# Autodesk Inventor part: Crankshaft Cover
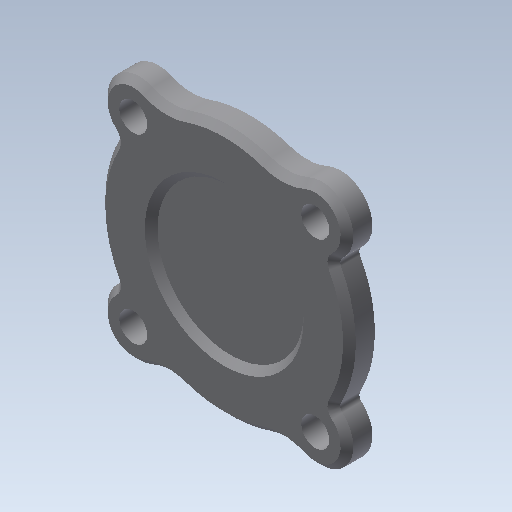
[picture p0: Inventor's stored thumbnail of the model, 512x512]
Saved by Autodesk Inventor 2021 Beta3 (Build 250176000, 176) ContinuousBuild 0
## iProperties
Created: 2013-05
Part Number: Crankshaft Cover
Material: Generic
Document SubType Name: Modeling
Designer: John
Density: 1 g/cm^3
Appearance: Default
Author: John
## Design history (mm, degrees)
sketch "Sketch1"
  geometry: C1 r 10.477 at (0, 0) reference; C2 r 0.965 at (9.093, -9.093) reference; C3 r 0.965 at (-9.093, 9.093) reference; C4 r 0.965 at (9.093, 9.093) reference; C5 r 0.965 at (-9.093, -9.093) reference; A1 r 3.175 centre (9.093, 9.093) between (11.169, 6.691) and (7.799, 11.992) reference; A2 r 5.08 centre (5.727, 16.631) between (4.073, 11.828) and (7.799, 11.992) reference; A3 r 12.509 centre (0, 0) between (4.073, 11.828) and (-4.073, 11.828) reference; A4 r 5.08 centre (-5.727, 16.631) between (-7.799, 11.992) and (-4.073, 11.828) reference; A5 r 3.175 centre (-9.093, 9.093) between (-7.799, 11.992) and (-11.169, 6.691) reference; A6 r 0.635 centre (-11.585, 6.211) between (-11.025, 5.911) and (-11.169, 6.691) reference; A7 r 12.509 centre (0, 0) between (-11.025, 5.911) and (-11.025, -5.911) reference; A8 r 0.635 centre (-11.585, -6.211) between (-11.169, -6.691) and (-11.025, -5.911) reference; A9 r 3.175 centre (-9.093, -9.093) between (-11.169, -6.691) and (-7.799, -11.992) reference; A10 r 5.08 centre (-5.727, -16.631) between (-4.073, -11.828) and (-7.799, -11.992) reference; A11 r 12.509 centre (0, 0) between (-4.073, -11.828) and (4.073, -11.828) reference; A12 r 5.08 centre (5.727, -16.631) between (7.799, -11.992) and (4.073, -11.828) reference; A13 r 3.175 centre (9.093, -9.093) between (7.799, -11.992) and (11.169, -6.691) reference; A14 r 0.635 centre (11.585, -6.211) between (11.025, -5.911) and (11.169, -6.691) reference; A15 r 12.509 centre (0, 0) between (11.025, -5.911) and (11.025, 5.911) reference; A16 r 0.635 centre (11.585, 6.211) between (11.169, 6.691) and (11.025, 5.911) reference; 1 further point
extrude "Extrusion1" new body sketch "Sketch1" distance "d0" = 2.54; taper "d1" = 0 deg
sketch "Sketch2"
  geometry: C1 r 10.477 at (0, 0) reference; C2 r 10.351 at (0, 0)
  constraints: 1 centre point, 1 coincident
  dimensions: "d2" = 0.127 radial gap between concentric circles of C1 C2
extrude "Extrusion2" join sketch "Sketch2" distance "d3" = 0.635; taper "d4" = 0 deg
sketch "Sketch3"
  geometry: C1 r 4 at (0, 0) reference; C2 r 4.026 at (0, 0); C3 r 6.566 at (0, 0)
  constraints: 2 centre point, 2 coincident
  dimensions: "d5" = 0.0254 radial gap between concentric circles of C1 C2; "d6" = 2.54 radial gap between concentric circles of C3 C2
extrude "Extrusion3" join sketch "Sketch3" distance "d7" = 3.175; taper "d8" = 0 deg
chamfer "Chamfer1" distance "d9" = 0.635; stored, may be unused: second distance "d10" = 3.175, angle "d11" = 45 deg
chamfer "Chamfer4" distance "d28" = 0.254; stored, may be unused: second distance "d29" = 3.175, angle "d30" = 45 deg
sketch "Sketch4"
  geometry: A1 r 3.175 centre (9.093, 9.093) between (11.169, 6.691) and (7.799, 11.992) reference; A2 r 3.175 centre (-9.093, 9.093) between (-7.799, 11.992) and (-11.169, 6.691) reference; A3 r 3.175 centre (-9.093, -9.093) between (-11.169, -6.691) and (-7.799, -11.992) reference; A4 r 3.175 centre (9.093, -9.093) between (7.799, -11.992) and (11.169, -6.691) reference
hole "Hole1" sketch "Sketch4" at (9.093, 9.093), (-9.093, 9.093), (-9.093, -9.093), (9.093, -9.093) diameter "d12" = 2.794; stored, may be unused: countersink angle "d16" = 82 deg, drill point angle "d18" = 118 deg; dims "d13" = 19.05, "d14" = 5.0546, "d15" = 6.35, "d17" = 25.4
sketch "Sketch5"
  geometry: C1 r 7.938 at (0, 0); A1 r 12.509 centre (0, 0) between (11.025, -5.911) and (11.025, 5.911) reference
  constraints: 1 centre point, 1 coincident
  dimensions: "d19" = 15.875 diameter of C1
extrude "Extrusion4" cut sketch "Sketch5" distance "d20" = 0.635; taper "d21" = 0 deg
chamfer "Chamfer2" distance "d22" = 0.635; stored, may be unused: second distance "d23" = 3.175, angle "d24" = 45 deg
chamfer "Chamfer3" distance "d25" = 0.635; stored, may be unused: second distance "d26" = 3.175, angle "d27" = 45 deg
body "Solid1"
node "Reference1"
node "Reference2"
node "Reference3"
